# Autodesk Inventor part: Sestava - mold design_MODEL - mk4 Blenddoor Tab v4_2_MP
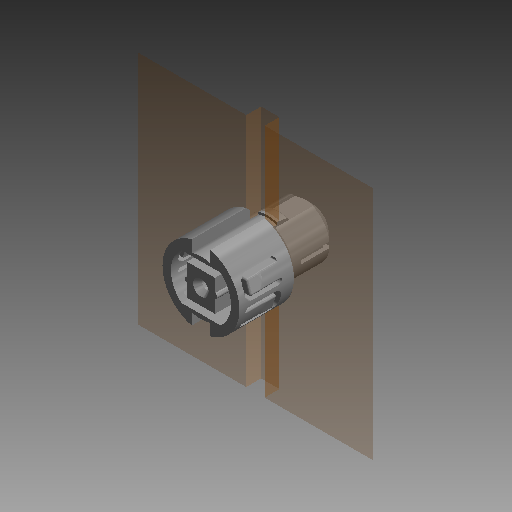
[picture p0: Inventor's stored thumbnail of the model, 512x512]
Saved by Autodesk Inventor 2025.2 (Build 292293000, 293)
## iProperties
Part Number: Sestava - mold design_MODEL - mk4 Blenddoor Tab v4_2_MP
Material: Generický
Document SubType Name: Modelování
Designer: Patrik
Appearance: Výchozí
Author: Patrik
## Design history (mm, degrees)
derived "MODEL - mk4 Blenddoor Tab v4_2.ipt"
node "Sestava - mold design_MODEL - mk4 Blenddoor Tab v4_2_WP"
node "Dělicí25" dims "Xmax" = 22.5, "Xmin" = -22.5, "Ymax" = 22.5, "Ymin" = -22.5, "Zmax" = 36, "Zmin" = -36
node "Dělicí26" dims "Xmax" = 22.5, "Xmin" = -22.5, "Ymax" = 22.5, "Ymin" = -22.5, "Zmax" = 36, "Zmin" = -36
node "Dělicí27" dims "Xmax" = 22.5, "Xmin" = -22.5, "Ymax" = 22.5, "Ymin" = -22.5, "Zmax" = 36, "Zmin" = -36
node "Dělicí28" dims "Xmax" = 22.5, "Xmin" = -22.5, "Ymax" = 22.5, "Ymin" = -22.5, "Zmax" = 36, "Zmin" = -36
node "Dělicí29" dims "Xmax" = 22.5, "Xmin" = -22.5, "Ymax" = 22.5, "Ymin" = -22.5, "Zmax" = 36, "Zmin" = -36
node "Dělicí30" dims "Xmax" = 22.5, "Xmin" = -22.5, "Ymax" = 22.5, "Ymin" = -22.5, "Zmax" = 36, "Zmin" = -36
node "Dělicí31" dims "Xmax" = 22.5, "Xmin" = -22.5, "Ymax" = 22.5, "Ymin" = -22.5, "Zmax" = 36, "Zmin" = -36
node "Dělicí32" dims "Xmax" = 22.5, "Xmin" = -22.5, "Ymax" = 22.5, "Ymin" = -22.5, "Zmax" = 36, "Zmin" = -36
node "Dělicí33" dims "Xmax" = 22.5, "Xmin" = -22.5, "Ymax" = 22.5, "Ymin" = -22.5, "Zmax" = 36, "Zmin" = -36
node "Dělicí34" dims "Xmax" = 22.5, "Xmin" = -22.5, "Ymax" = 22.5, "Ymin" = -22.5, "Zmax" = 36, "Zmin" = -36
node "Dělicí35" dims "Xmax" = 22.5, "Xmin" = -22.5, "Ymax" = 22.5, "Ymin" = -22.5, "Zmax" = 36, "Zmin" = -36
node "Dělicí36" dims "Xmax" = 22.5, "Xmin" = -22.5, "Ymax" = 22.5, "Ymin" = -22.5, "Zmax" = 36, "Zmin" = -36
node "Dělicí37" dims "Xmax" = 22.5, "Xmin" = -22.5, "Ymax" = 22.5, "Ymin" = -22.5, "Zmax" = 36, "Zmin" = -36
node "Dělicí38" dims "Xmax" = 22.5, "Xmin" = -22.5, "Ymax" = 22.5, "Ymin" = -22.5, "Zmax" = 36, "Zmin" = -36
node "Dělicí39" dims "Xmax" = 22.5, "Xmin" = -22.5, "Ymax" = 22.5, "Ymin" = -22.5, "Zmax" = 36, "Zmin" = -36
node "Dělicí40" dims "Xmax" = 22.5, "Xmin" = -22.5, "Ymax" = 22.5, "Ymin" = -22.5, "Zmax" = 36, "Zmin" = -36
node "Dělicí41" dims "Xmax" = 22.5, "Xmin" = -22.5, "Ymax" = 22.5, "Ymin" = -22.5, "Zmax" = 36, "Zmin" = -36
node "Dělicí42" dims "Xmax" = 22.5, "Xmin" = -22.5, "Ymax" = 22.5, "Ymin" = -22.5, "Zmax" = 36, "Zmin" = -36
node "Dělicí43" dims "Xmax" = 22.5, "Xmin" = -22.5, "Ymax" = 22.5, "Ymin" = -22.5, "Zmax" = 36, "Zmin" = -36
node "Dělicí44" dims "Xmax" = 22.5, "Xmin" = -22.5, "Ymax" = 22.5, "Ymin" = -22.5, "Zmax" = 36, "Zmin" = -36
node "Dělicí45" dims "Xmax" = 22.5, "Xmin" = -22.5, "Ymax" = 22.5, "Ymin" = -22.5, "Zmax" = 36, "Zmin" = -36
node "Dělicí46" dims "Xmax" = 22.5, "Xmin" = -22.5, "Ymax" = 22.5, "Ymin" = -22.5, "Zmax" = 36, "Zmin" = -36
node "Dělicí47" dims "Xmax" = 22.5, "Xmin" = -22.5, "Ymax" = 22.5, "Ymin" = -22.5, "Zmax" = 36, "Zmin" = -36
node "Dělicí48" dims "Xmax" = 22.5, "Xmin" = -22.5, "Ymax" = 22.5, "Ymin" = -22.5, "Zmax" = 36, "Zmin" = -36
feature "Oddělení dutiny3"
node "Objemová tělesa"
node "Povrchová tělesa"
feature "Těleso1::MODEL - mk4 Blenddoor Tab v4_2.ipt"
tag "Prvek štítků1"
feature "Těleso1::Sestava - mold design_MODEL - mk4 Blenddoor Tab v4_"
tag "Prvek štítků2"
node "Těleso7"
node "Těleso8"
node "Těleso1"
feature "MODEL - mk4 Blenddoor Tab v4_2.ipt_Tělesa"
node "Těleso1_1"
feature "Sestava - mold design_MODEL - mk4 Blenddoor Tab v4_2_WP_Těle"
feature "Plocha25"
node "Povrch25"
feature "Plocha26"
node "Povrch26"
feature "Plocha27"
node "Povrch27"
feature "Plocha28"
node "Povrch28"
feature "Plocha29"
node "Povrch29"
feature "Plocha30"
node "Povrch30"
feature "Plocha31"
node "Povrch31"
feature "Plocha32"
node "Povrch32"
feature "Plocha33"
node "Povrch33"
feature "Plocha34"
node "Povrch34"
feature "Plocha35"
node "Povrch35"
feature "Plocha36"
node "Povrch36"
feature "Plocha37"
node "Povrch37"
feature "Plocha38"
node "Povrch38"
feature "Plocha39"
node "Povrch39"
feature "Plocha40"
node "Povrch40"
feature "Plocha41"
node "Povrch41"
feature "Plocha42"
node "Povrch42"
feature "Plocha43"
node "Povrch43"
feature "Plocha44"
node "Povrch44"
feature "Plocha45"
node "Povrch45"
feature "Plocha46"
node "Povrch46"
feature "Plocha47"
node "Povrch47"
feature "Plocha48"
node "Povrch48"
other parameters: "d1" = 22.5, "d2" = 22.5, "d3" = 22.5, "d4" = 22.5, "d5" = 72, "d6" = 0
